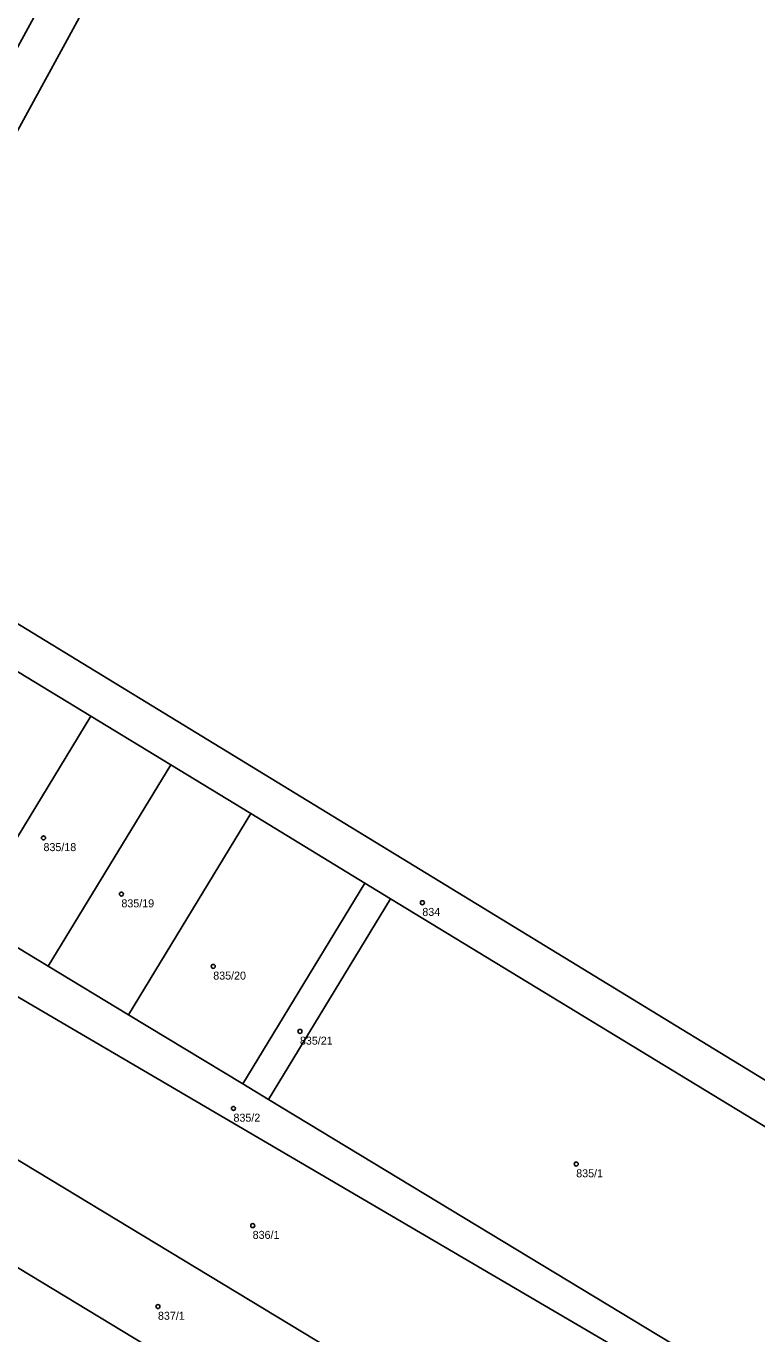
# Model space of a CAD drawing. Extents: x -550098 to -546083, y -1127254 to -1124489.
# Drawn here: x -547539.8 to -547448.4, y -1125475.8 to -1125312.4 of the extents above; entities that cross this region are included whole.
import ezdxf

# ---------------------------------------------------------------- set-up
doc = ezdxf.new("R2010")
doc.units = 0
doc.layers.add('Definiční body', color=7, linetype='Continuous')
doc.layers.add('Polygon parcely', color=7, linetype='Continuous')

msp = doc.modelspace()

# ---------------------------------------------------------------- linework, layer by layer
at = {"layer": 'Definiční body'}
for centre in [(-547537.59, -1125413.83994), (-547527.85, -1125420.86994), (-547490.23, -1125421.93994), (-547516.37, -1125429.89994), (-547505.53, -1125438.02994), (-547513.84, -1125447.65994), (-547470.99, -1125454.60994), (-547511.44, -1125462.30994), (-547523.28, -1125472.41994)]:
    msp.add_circle(centre, 0.25, dxfattribs=at)
at = {"layer": 'Polygon parcely'}
for points in [[(-547314.83, -1125057.61), (-547460.83, -1125194.78), (-547469.67, -1125203.97), (-547481.09, -1125217.99), (-547498.9, -1125240.26), (-547513.77, -1125265.39), (-547572.86, -1125373.58), (-547583.27, -1125392.95), (-547594.34, -1125413.55), (-547599, -1125422.24), (-547604.99, -1125433.37), (-547613.05, -1125448.39), (-547622.42, -1125465.83), (-547640, -1125498.55)], [(-547640, -1125498.55), (-547622.42, -1125465.83), (-547613.05, -1125448.39), (-547604.99, -1125433.37), (-547599, -1125422.24), (-547594.34, -1125413.55), (-547583.27, -1125392.95), (-547572.86, -1125373.58), (-547513.77, -1125265.39), (-547498.9, -1125240.26), (-547481.09, -1125217.99), (-547469.67, -1125203.97), (-547460.83, -1125194.78), (-547314.83, -1125057.61)], [(-547637.68, -1125504.69), (-547605.06, -1125444.09), (-547604.12, -1125442.34), (-547598.79, -1125432.44), (-547593.34, -1125422.32), (-547585.41, -1125407.58), (-547582.56, -1125402.3), (-547571.34, -1125381.46), (-547563.23, -1125366.39), (-547511.3, -1125271.31), (-547509.63, -1125268.24), (-547497.04, -1125246.89), (-547495.09, -1125243.59), (-547477.63, -1125221.34), (-547471.8, -1125214.35), (-547465.82, -1125207.19), (-547457.21, -1125198.27), (-547444.5, -1125186.38)]]:
    msp.add_lwpolyline(points, dxfattribs=at)
for points in [[(-547421.79, -1125459.74), (-547411.72, -1125459.35), (-547314.89, -1125390.76), (-547511.3, -1125271.31), (-547563.23, -1125366.39), (-547560.75, -1125374.92)], [(-547531.68, -1125398.64), (-547521.69, -1125404.72), (-547511.69, -1125410.8), (-547497.42, -1125419.49), (-547494.2, -1125421.44), (-547425.71, -1125463.11), (-547423.55, -1125471.51), (-547419.21, -1125474.16), (-547411.12, -1125466.23), (-547421.79, -1125459.74), (-547560.75, -1125374.92), (-547563.23, -1125366.39), (-547571.34, -1125381.46), (-547563.26, -1125379.43), (-547551.68, -1125386.48), (-547541.68, -1125392.56)], [(-547547, -1125423.82), (-547531.68, -1125398.64), (-547541.68, -1125392.56), (-547557.01, -1125417.76)], [(-547536.99, -1125429.88), (-547521.69, -1125404.72), (-547531.68, -1125398.64), (-547547, -1125423.82)], [(-547585.41, -1125407.58), (-547436.19, -1125494.99), (-547434.53, -1125491.89), (-547509.47, -1125446.53), (-547512.69, -1125444.59), (-547526.98, -1125435.94), (-547536.99, -1125429.88), (-547547, -1125423.82), (-547557.01, -1125417.76), (-547567.02, -1125411.7), (-547582.56, -1125402.3)], [(-547526.98, -1125435.94), (-547511.69, -1125410.8), (-547521.69, -1125404.72), (-547536.99, -1125429.88)], [(-547585.41, -1125407.58), (-547593.34, -1125422.32), (-547445.29, -1125511.89), (-547436.19, -1125494.99)], [(-547512.69, -1125444.59), (-547497.42, -1125419.49), (-547511.69, -1125410.8), (-547526.98, -1125435.94)], [(-547509.47, -1125446.53), (-547494.2, -1125421.44), (-547497.42, -1125419.49), (-547512.69, -1125444.59)], [(-547509.47, -1125446.53), (-547434.53, -1125491.89), (-547423.55, -1125471.51), (-547425.71, -1125463.11), (-547494.2, -1125421.44)], [(-547445.29, -1125511.89), (-547593.34, -1125422.32), (-547598.79, -1125432.44), (-547450.77, -1125522.07)], [(-547456.1, -1125531.98), (-547450.77, -1125522.07), (-547598.79, -1125432.44), (-547604.12, -1125442.34)]]:
    msp.add_lwpolyline(points, close=True, dxfattribs=at)

# ---------------------------------------------------------------- texts
at = {"layer": 'Definiční body'}
for s, p in [('835/18', (-547537.59, -1125415.496)), ('835/19', (-547527.85, -1125422.526)), ('834', (-547490.23, -1125423.596)), ('835/20', (-547516.37, -1125431.556)), ('835/21', (-547505.53, -1125439.686)), ('835/2', (-547513.84, -1125449.316)), ('835/1', (-547470.99, -1125456.266)), ('836/1', (-547511.44, -1125463.966)), ('837/1', (-547523.28, -1125474.076))]:
    msp.add_text(s, height=0.999996, dxfattribs=at).set_placement(p)

doc.saveas('drawing.dxf')
